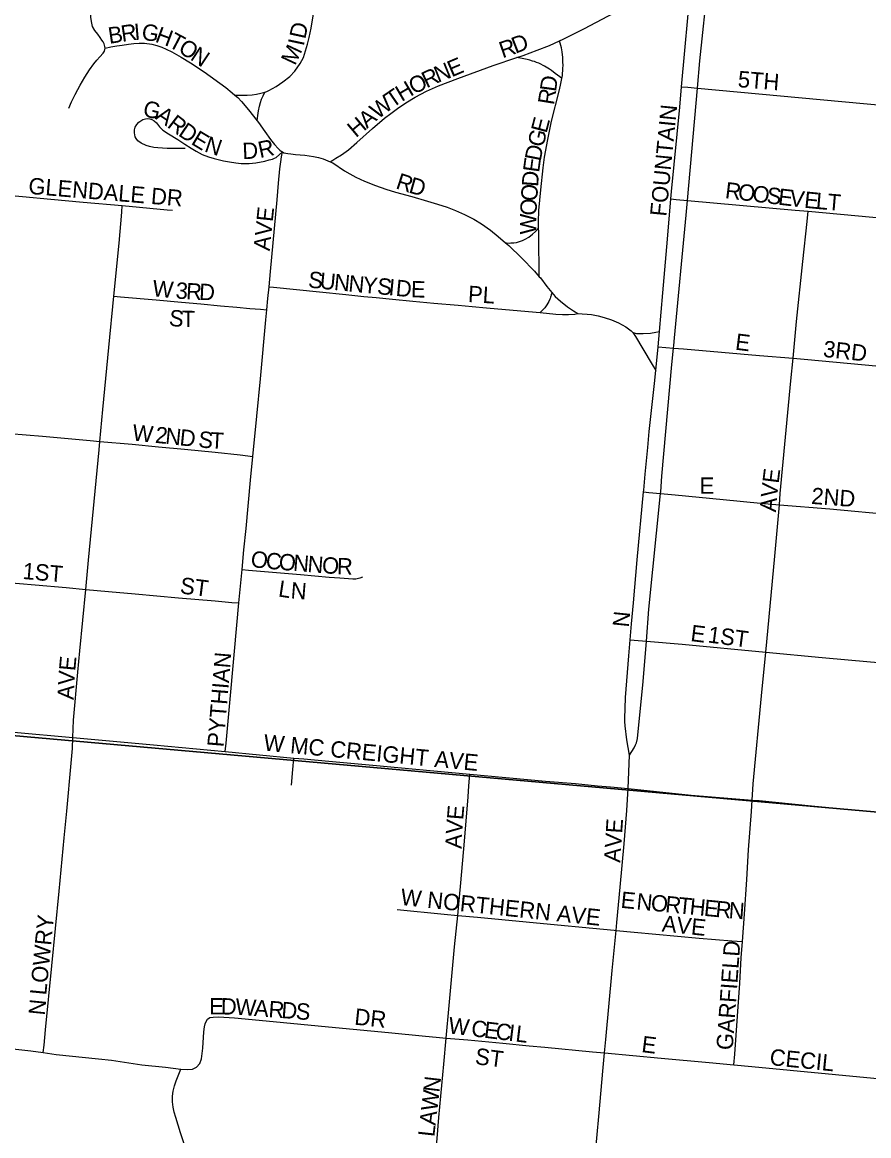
# Model space of a CAD drawing. Extents: x -209 to 4852, y 0 to 905.
# Drawn here: x 111.72 to 121.51, y 290.63 to 303.5 of the extents above; entities that cross this region are included whole.
import ezdxf

# ---------------------------------------------------------------- set-up
doc = ezdxf.new("R2010")
doc.units = 0
for name, color, linetype in [('GM_X_Airport_Location_Class_2', 7, 'Continuous'), ('GM_X_Airport_Location_Class_3', 7, 'Continuous'), ('GM_X_Minor_River', 7, 'Continuous')]:
    doc.layers.add(name, color=color, linetype=linetype)

msp = doc.modelspace()

# ---------------------------------------------------------------- linework, layer by layer
at = {"layer": 'GM_X_Airport_Location_Class_2'}
for points in [[(112.68, 303.197), (112.678, 303.217), (112.67, 303.249), (112.659, 303.27), (112.645, 303.292), (112.624, 303.321), (112.596, 303.36), (112.563, 303.403), (112.537, 303.449), (112.522, 303.506), (112.517, 303.556), (112.517, 303.606), (112.523, 303.652), (112.534, 303.683), (112.554, 303.734), (112.604, 303.849), (112.654, 303.967), (112.714, 304.107), (112.754, 304.205), (112.805, 304.329), (112.845, 304.427), (112.865, 304.477), (112.892, 304.544), (112.913, 304.609)], [(114.528, 302.69), (114.549, 302.698), (114.574, 302.71), (114.659, 302.756), (114.735, 302.809), (114.814, 302.871), (114.873, 302.931), (114.936, 303.019), (114.972, 303.092), (114.998, 303.167), (115.021, 303.246), (115.038, 303.322), (115.061, 303.43), (115.087, 303.572), (115.133, 303.782), (115.181, 304), (115.258, 304.315), (115.274, 304.381)], [(117.931, 303.283), (117.973, 303.302), (118.223, 303.426), (118.491, 303.566), (118.736, 303.686), (118.988, 303.821), (119.004, 303.831), (119.013, 303.838), (119.019, 303.842), (119.025, 303.848), (119.033, 303.854), (119.044, 303.865), (119.054, 303.876), (119.059, 303.884), (119.063, 303.889), (119.066, 303.893), (119.069, 303.897), (119.072, 303.904), (119.081, 303.925), (119.115, 304)], [(119.343, 302.753), (119.453, 303.973)], [(119.526, 302.737), (119.554, 303.051), (119.651, 303.964)], [(117.438, 303.089), (117.511, 303.114), (117.673, 303.173), (117.817, 303.23), (117.931, 303.283)], [(117.96, 302.847), (117.962, 302.861), (117.965, 302.882), (117.972, 302.964), (117.973, 303.002), (117.972, 303.038), (117.97, 303.089), (117.963, 303.154), (117.954, 303.202), (117.939, 303.257), (117.931, 303.283)], [(112.26, 302.506), (112.293, 302.578), (112.333, 302.662), (112.365, 302.719), (112.392, 302.772), (112.445, 302.861), (112.5, 302.946), (112.551, 303.017), (112.585, 303.058), (112.62, 303.098), (112.657, 303.139), (112.672, 303.165), (112.678, 303.182), (112.68, 303.197)], [(112.68, 303.197), (112.749, 303.212), (112.817, 303.225), (112.879, 303.234), (112.951, 303.245), (113.013, 303.253), (113.073, 303.257), (113.138, 303.257), (113.222, 303.245), (113.278, 303.23), (113.335, 303.21), (113.386, 303.188), (113.451, 303.157), (113.56, 303.095), (113.666, 303.03), (113.824, 302.924), (114.075, 302.744), (114.151, 302.681), (114.182, 302.654)], [(115.281, 301.885), (115.314, 301.903), (115.349, 301.926), (115.413, 301.967), (115.493, 302.025), (115.591, 302.108), (115.773, 302.268), (115.911, 302.39), (115.983, 302.444), (116.059, 302.502), (116.156, 302.566), (116.263, 302.631), (116.396, 302.7), (116.534, 302.761), (116.645, 302.804), (116.757, 302.846), (117.165, 302.997), (117.438, 303.089)], [(117.96, 302.847), (117.935, 302.867), (117.884, 302.906), (117.841, 302.938), (117.816, 302.955), (117.796, 302.968), (117.778, 302.98), (117.76, 302.991), (117.743, 302.999), (117.717, 303.013), (117.693, 303.024), (117.668, 303.033), (117.644, 303.043), (117.621, 303.049), (117.588, 303.059), (117.558, 303.068), (117.502, 303.08), (117.438, 303.089)], [(117.689, 301.117), (117.689, 301.191), (117.695, 301.323), (117.715, 301.562), (117.743, 301.817), (117.759, 301.94), (117.796, 302.141), (117.84, 302.353), (117.927, 302.701), (117.944, 302.771), (117.957, 302.828), (117.96, 302.847)], [(114.182, 302.654), (114.275, 302.654), (114.324, 302.654), (114.38, 302.658), (114.429, 302.665), (114.479, 302.676), (114.528, 302.69)], [(114.182, 302.654), (114.213, 302.628), (114.258, 302.582), (114.338, 302.487), (114.438, 302.357)], [(114.438, 302.357), (114.447, 302.421), (114.454, 302.473), (114.465, 302.528), (114.476, 302.569), (114.49, 302.609), (114.507, 302.648), (114.528, 302.69)], [(119.22, 301.456), (119.227, 301.541), (119.321, 302.516), (119.343, 302.753)], [(119.343, 302.753), (119.415, 302.747), (119.526, 302.737)], [(119.411, 301.438), (119.526, 302.737)], [(119.526, 302.737), (121.445, 302.558), (123.103, 302.408), (123.276, 302.392)], [(113.605, 302.04), (113.397, 302.04), (113.292, 302.045), (113.245, 302.05), (113.195, 302.062), (113.155, 302.074), (113.099, 302.101), (113.06, 302.127), (113.039, 302.154), (113.03, 302.173), (113.023, 302.195), (113.019, 302.221), (113.021, 302.256), (113.029, 302.284), (113.047, 302.316), (113.071, 302.342), (113.095, 302.36), (113.118, 302.373), (113.146, 302.383), (113.171, 302.387), (113.196, 302.383), (113.22, 302.375), (113.246, 302.36), (113.275, 302.334), (113.311, 302.288), (113.349, 302.249), (113.415, 302.207), (113.52, 302.141), (113.603, 302.09), (113.677, 302.041), (113.733, 302.006), (113.803, 301.97), (113.875, 301.942), (113.942, 301.922), (114.048, 301.897), (114.12, 301.883), (114.192, 301.871), (114.254, 301.866), (114.3, 301.866), (114.346, 301.867), (114.423, 301.874), (114.527, 301.893), (114.577, 301.906), (114.617, 301.917), (114.637, 301.925), (114.656, 301.936), (114.73, 302)], [(114.438, 302.357), (114.452, 302.339), (114.525, 302.235), (114.593, 302.143), (114.637, 302.083), (114.68, 302.038), (114.699, 302.021), (114.714, 302.009), (114.73, 302)], [(114.575, 300.44), (114.592, 300.616), (114.671, 301.445), (114.686, 301.636), (114.702, 301.805), (114.71, 301.884), (114.718, 301.941), (114.73, 302)], [(114.73, 302), (114.748, 301.99), (114.769, 301.984), (114.793, 301.979), (114.826, 301.975), (114.88, 301.97), (114.99, 301.962), (115.091, 301.946), (115.147, 301.933), (115.201, 301.918), (115.256, 301.897), (115.281, 301.885)], [(115.281, 301.885), (115.311, 301.871), (115.449, 301.78), (115.509, 301.745), (115.579, 301.709), (115.679, 301.662), (115.805, 301.611), (115.925, 301.569), (116.036, 301.534), (116.226, 301.483), (116.406, 301.431), (116.524, 301.396), (116.634, 301.36), (116.731, 301.323), (116.836, 301.275), (116.942, 301.222), (117.03, 301.169), (117.133, 301.094), (117.223, 301.021), (117.308, 300.947)], [(111.409, 301.513), (111.475, 301.507), (111.728, 301.484), (112.053, 301.454), (112.429, 301.419), (112.879, 301.378)], [(112.783, 300.332), (112.844, 300.944), (112.874, 301.304), (112.879, 301.378)], [(112.879, 301.378), (113.397, 301.331), (113.458, 301.325)], [(119.086, 299.922), (119.128, 300.371), (119.181, 300.989), (119.22, 301.456)], [(119.22, 301.456), (119.279, 301.45), (119.411, 301.438)], [(119.25, 299.733), (119.252, 299.761), (119.261, 299.851), (119.396, 301.269), (119.411, 301.438)], [(119.411, 301.438), (120.656, 301.327), (120.805, 301.313)], [(120.631, 299.614), (120.672, 300.038), (120.744, 300.733), (120.793, 301.196), (120.805, 301.313)], [(120.805, 301.313), (122.3, 301.176), (122.981, 301.11), (123.139, 301.095)], [(117.308, 300.947), (117.319, 300.947), (117.35, 300.946), (117.371, 300.947), (117.383, 300.948), (117.39, 300.948), (117.398, 300.949), (117.406, 300.95), (117.435, 300.954), (117.469, 300.962), (117.505, 300.976), (117.536, 300.992), (117.576, 301.014), (117.622, 301.047), (117.655, 301.078), (117.674, 301.099), (117.681, 301.106), (117.689, 301.117)], [(117.699, 300.556), (117.699, 300.581), (117.698, 300.687), (117.694, 300.901), (117.694, 301.016), (117.693, 301.047), (117.692, 301.075), (117.689, 301.117)], [(117.308, 300.947), (117.345, 300.916), (117.493, 300.776), (117.645, 300.621), (117.699, 300.556)], [(117.699, 300.556), (117.712, 300.543), (117.785, 300.444), (117.844, 300.375)], [(112.621, 298.654), (112.653, 299.024), (112.737, 299.858), (112.771, 300.214), (112.783, 300.332)], [(112.783, 300.332), (112.857, 300.325), (113.272, 300.288), (113.562, 300.263), (113.787, 300.243), (114.015, 300.222), (114.205, 300.205), (114.352, 300.191), (114.476, 300.18), (114.55, 300.173)], [(114.55, 300.173), (114.562, 300.305), (114.575, 300.44)], [(114.575, 300.44), (114.627, 300.435), (115.158, 300.382), (115.463, 300.351), (115.672, 300.33), (115.815, 300.316), (116.004, 300.297), (116.239, 300.275), (116.48, 300.253), (116.762, 300.227), (116.923, 300.213), (117.088, 300.198), (117.308, 300.178), (117.71, 300.142)], [(117.844, 300.375), (117.843, 300.37), (117.842, 300.368), (117.84, 300.359), (117.837, 300.348), (117.834, 300.338), (117.833, 300.332), (117.831, 300.328), (117.83, 300.325), (117.828, 300.319), (117.824, 300.307), (117.819, 300.296), (117.808, 300.272), (117.796, 300.25), (117.786, 300.232), (117.779, 300.221), (117.771, 300.209), (117.762, 300.198), (117.747, 300.182), (117.71, 300.142)], [(117.844, 300.375), (117.882, 300.33), (117.943, 300.275), (118.025, 300.208), (118.093, 300.161), (118.145, 300.13)], [(114.389, 298.479), (114.436, 298.945), (114.475, 299.378), (114.54, 300.058), (114.55, 300.173)], [(117.71, 300.142), (117.888, 300.126), (117.967, 300.121), (118.035, 300.121), (118.111, 300.126), (118.145, 300.13)], [(118.145, 300.13), (118.195, 300.129), (118.252, 300.126), (118.303, 300.119), (118.379, 300.105), (118.45, 300.087), (118.535, 300.057), (118.615, 300.024), (118.697, 299.979), (118.731, 299.955), (118.759, 299.931), (118.778, 299.912)], [(118.778, 299.912), (118.822, 299.902), (118.9, 299.899), (118.982, 299.905), (119.044, 299.915), (119.086, 299.922)], [(118.778, 299.912), (118.81, 299.866), (118.894, 299.722), (119.003, 299.544), (119.046, 299.475)], [(119.071, 299.747), (119.086, 299.922)], [(119.046, 299.475), (119.071, 299.747)], [(119.071, 299.747), (119.162, 299.74), (119.25, 299.733)], [(119.101, 298.052), (119.103, 298.072), (119.116, 298.252), (119.229, 299.543), (119.25, 299.733)], [(119.25, 299.733), (119.366, 299.724), (120.244, 299.647), (120.631, 299.614)], [(120.473, 297.922), (120.484, 298.052), (120.605, 299.352), (120.631, 299.614)], [(120.631, 299.614), (120.803, 299.599), (121.919, 299.498), (122.284, 299.46), (122.776, 299.416), (122.969, 299.399)], [(118.904, 298.071), (118.905, 298.089), (118.923, 298.274), (118.952, 298.583), (118.97, 298.769), (119.032, 299.324), (119.046, 299.475)], [(111.149, 298.783), (111.212, 298.777), (111.58, 298.745), (111.957, 298.713), (112.507, 298.664), (112.621, 298.654)], [(112.458, 296.944), (112.49, 297.282), (112.611, 298.557), (112.621, 298.654)], [(112.621, 298.654), (112.995, 298.621), (113.298, 298.592), (113.6, 298.563), (113.951, 298.529), (114.241, 298.497), (114.389, 298.479)], [(114.264, 297.173), (114.286, 297.4), (114.311, 297.649), (114.363, 298.205), (114.389, 298.479)], [(118.749, 296.362), (118.764, 296.544), (118.786, 296.79), (118.829, 297.285), (118.904, 298.071)], [(118.904, 298.071), (118.965, 298.065), (119.101, 298.052)], [(118.936, 296.347), (118.965, 296.714), (119.101, 298.052)], [(119.101, 298.052), (119.268, 298.036), (119.823, 297.981), (120.257, 297.94), (120.473, 297.922)], [(120.318, 296.219), (120.329, 296.336), (120.419, 297.329), (120.473, 297.922)], [(120.473, 297.922), (121.057, 297.873), (121.801, 297.804), (122.795, 297.717)], [(114.226, 296.788), (114.264, 297.173)], [(114.264, 297.173), (114.338, 297.167), (114.661, 297.14), (114.94, 297.116), (115.271, 297.085), (115.393, 297.076), (115.545, 297.066), (115.561, 297.066), (115.577, 297.067), (115.594, 297.07), (115.61, 297.073), (115.629, 297.079), (115.66, 297.089)], [(110.989, 297.08), (111.029, 297.076), (111.142, 297.064), (111.512, 297.029), (111.873, 296.995), (112.229, 296.966), (112.458, 296.944)], [(112.308, 295.231), (112.315, 295.432), (112.365, 295.986), (112.389, 296.233), (112.458, 296.944)], [(112.458, 296.944), (112.721, 296.92), (113.027, 296.892), (113.531, 296.847), (113.953, 296.81), (114.147, 296.794), (114.226, 296.788)], [(114.069, 295.069), (114.079, 295.167), (114.116, 295.548), (114.176, 296.231), (114.226, 296.788)], [(118.741, 295.027), (118.711, 295.207), (118.693, 295.367), (118.688, 295.416), (118.687, 295.454), (118.69, 295.566), (118.695, 295.693), (118.733, 296.175), (118.749, 296.362)], [(118.741, 295.027), (118.794, 295.112), (118.811, 295.148), (118.821, 295.171), (118.833, 295.221), (118.899, 295.881), (118.936, 296.347)], [(118.749, 296.362), (118.796, 296.358), (118.936, 296.347)], [(118.936, 296.347), (119.351, 296.31), (120.318, 296.219)], [(120.159, 294.509), (120.172, 294.696), (120.268, 295.713), (120.318, 296.219)], [(120.318, 296.219), (120.967, 296.157), (121.526, 296.106), (121.837, 296.078), (122.621, 296.021)], [(110.822, 295.363), (111.625, 295.294), (112.308, 295.231)], [(111.966, 291.591), (111.975, 291.675), (111.992, 291.854), (112.067, 292.593), (112.109, 293.024), (112.149, 293.456), (112.209, 294.073), (112.237, 294.382), (112.288, 294.935), (112.303, 295.105), (112.308, 295.231)], [(112.308, 295.231), (113.239, 295.147), (114.069, 295.069)], [(114.069, 295.069), (114.863, 294.995)], [(114.835, 294.682), (114.851, 294.863), (114.863, 294.995)], [(114.863, 294.995), (114.977, 294.984), (115.266, 294.957), (115.816, 294.907), (116.065, 294.884), (116.897, 294.808)], [(118.727, 294.641), (118.741, 295.027)], [(116.757, 293.176), (116.766, 293.265), (116.793, 293.553), (116.835, 294.035), (116.876, 294.546), (116.886, 294.673), (116.897, 294.808)], [(116.897, 294.808), (117.77, 294.729), (118.117, 294.699), (118.373, 294.675), (118.521, 294.662), (118.727, 294.641)], [(118.586, 293.002), (118.595, 293.095), (118.634, 293.504), (118.68, 294.002), (118.71, 294.387), (118.727, 294.641)], [(118.727, 294.641), (119.452, 294.567), (120.159, 294.509)], [(120.047, 292.873), (120.071, 293.19), (120.097, 293.592), (120.118, 293.935), (120.15, 294.377), (120.159, 294.509)], [(120.159, 294.509), (120.239, 294.504), (120.843, 294.443), (121.935, 294.339), (122.283, 294.308), (122.453, 294.293)], [(116.055, 293.243), (116.598, 293.19), (116.757, 293.176)], [(116.623, 291.758), (116.659, 292.136), (116.72, 292.815), (116.757, 293.176)], [(116.757, 293.176), (116.984, 293.156), (117.828, 293.075), (118.319, 293.028), (118.564, 293.004), (118.586, 293.002)], [(118.453, 291.587), (118.467, 291.742), (118.541, 292.541), (118.586, 293.002)], [(118.586, 293.002), (118.795, 292.981), (119.294, 292.936), (119.548, 292.913), (119.925, 292.883), (120.047, 292.873)], [(119.948, 291.449), (119.957, 291.574), (119.988, 292.013), (120.015, 292.394), (120.033, 292.687), (120.047, 292.873)], [(113.555, 291.401), (113.632, 291.394), (113.69, 291.399), (113.738, 291.424), (113.774, 291.466), (113.794, 291.519), (113.811, 291.643), (113.823, 291.832), (113.83, 291.887), (113.836, 291.923), (113.848, 291.951), (113.866, 291.976), (113.89, 291.995)], [(113.89, 291.995), (113.928, 292), (113.991, 292.003), (114.176, 291.992), (114.544, 291.958), (115.342, 291.881), (115.955, 291.822), (116.385, 291.78), (116.508, 291.769), (116.623, 291.758)], [(110.482, 291.757), (110.633, 291.741), (111.436, 291.655), (111.823, 291.61), (111.966, 291.591)], [(116.475, 290.093), (116.519, 290.597), (116.538, 290.842), (116.594, 291.457), (116.623, 291.758)], [(116.623, 291.758), (116.871, 291.738), (117.278, 291.7), (117.581, 291.671), (117.763, 291.654), (118.315, 291.6), (118.453, 291.587)], [(111.966, 291.591), (112.116, 291.57), (112.603, 291.52), (112.753, 291.505), (113.107, 291.449), (113.378, 291.424), (113.555, 291.401)], [(118.303, 289.934), (118.311, 290.043), (118.336, 290.308), (118.391, 290.894), (118.434, 291.377), (118.453, 291.587)], [(118.453, 291.587), (119.108, 291.528), (119.663, 291.477), (119.948, 291.449)], [(119.948, 291.449), (120.154, 291.43), (121.566, 291.294), (121.996, 291.253), (122.145, 291.24), (122.235, 291.231)], [(113.908, 289.721), (113.862, 289.837), (113.829, 289.921), (113.792, 290.03), (113.724, 290.198), (113.635, 290.426), (113.554, 290.662), (113.497, 290.841), (113.479, 290.901), (113.466, 290.961), (113.459, 291.023), (113.461, 291.086), (113.469, 291.147), (113.483, 291.207), (113.503, 291.265), (113.555, 291.401)]]:
    msp.add_lwpolyline(points, dxfattribs=at)
at = {"layer": 'GM_X_Minor_River'}
for points in [[(112.672, 315.623), (132.725, 313.81), (130.833, 293.553), (110.863, 295.32)], [(110.863, 295.32), (130.833, 293.553), (129.104, 273.545), (108.909, 275.428)]]:
    msp.add_lwpolyline(points, close=True, dxfattribs=at)

# ---------------------------------------------------------------- texts
at = {"layer": 'GM_X_Airport_Location_Class_3'}
for s, height, rotation, p in [('B', 0.189, 8.3602, (112.73, 303.248)), ('R', 0.189, 8.3362, (112.878, 303.27)), ('I', 0.189, 5.0757, (113.024, 303.291)), ('G', 0.189, 350.9365, (113.094, 303.299)), ('H', 0.189, 339.6845, (113.249, 303.275)), ('D', 0.189, 77.6229, (114.993, 303.296)), ('T', 0.189, 332.1397, (113.4, 303.22)), ('O', 0.189, 327.4132, (113.514, 303.16)), ('I', 0.189, 78.0535, (114.976, 303.215)), ('R', 0.189, 19.0264, (117.274, 303.08)), ('D', 0.189, 21.2096, (117.423, 303.132)), ('N', 0.189, 326.4373, (113.654, 303.071)), ('M', 0.189, 64.8687, (114.876, 302.989)), ('N', 0.189, 22.0734, (116.529, 302.796)), ('E', 0.189, 22.9431, (116.686, 302.86)), ('O', 0.189, 26.9462, (116.249, 302.658)), ('R', 0.189, 25.4247, (116.396, 302.733)), ('5TH', 0.1894, 355.4282, (119.988, 302.748)), ('H', 0.189, 30.4578, (116.108, 302.575)), ('D', 0.189, 82.1107, (117.891, 302.688)), ('W', 0.189, 38.0033, (115.833, 302.37)), ('T', 0.189, 34.607, (116.001, 302.501)), ('R', 0.189, 80.7812, (117.867, 302.535)), ('G', 0.189, 346.7219, (113.107, 302.416)), ('A', 0.189, 325.6491, (113.252, 302.386)), ('FOUNTAIN', 0.1894, 84.3612, (119.166, 301.248)), ('R', 0.189, 322.5425, (113.388, 302.293)), ('H', 0.189, 39.9707, (115.579, 302.157)), ('A', 0.189, 39.9707, (115.707, 302.264)), ('E', 0.189, 75.3009, (117.782, 302.207)), ('D', 0.189, 325.7315, (113.516, 302.195)), ('E', 0.189, 328.9183, (113.664, 302.095)), ('G', 0.189, 77.3527, (117.746, 302.046)), ('N', 0.189, 341.4934, (113.819, 302.007)), ('R', 0.189, 12.1769, (114.471, 301.927)), ('D', 0.189, 2.6671, (114.271, 301.915)), ('D', 0.189, 78.8272, (117.714, 301.884)), ('E', 0.189, 82.2447, (117.696, 301.755)), ('R', 0.189, 342.0259, (116.03, 301.58)), ('D', 0.189, 85.8443, (117.684, 301.592)), ('GLENDALE DR', 0.18939, 355.2836, (111.789, 301.515)), ('D', 0.189, 344.2388, (116.18, 301.531)), ('O', 0.189, 86.0405, (117.673, 301.426)), ('R', 0.189, 353.1341, (119.839, 301.465)), ('O', 0.189, 353.1408, (119.988, 301.447)), ('O', 0.189, 353.1216, (120.154, 301.427)), ('S', 0.189, 353.1421, (120.319, 301.407)), ('E', 0.189, 353.1519, (120.452, 301.391)), ('V', 0.189, 353.1755, (120.584, 301.375)), ('E', 0.189, 354.3007, (120.754, 301.355)), ('L', 0.189, 355.1896, (120.89, 301.341)), ('T', 0.189, 355.2142, (121.023, 301.33)), ('AVE', 0.1894, 84.0895, (114.583, 300.85)), ('O', 0.189, 87.7478, (117.666, 301.261)), ('W', 0.189, 89.9159, (117.666, 301.046)), ('S', 0.189, 354.6102, (115.022, 300.432)), ('U', 0.189, 354.6207, (115.155, 300.419)), ('N', 0.189, 354.6312, (115.321, 300.404)), ('N', 0.189, 354.6156, (115.487, 300.388)), ('W', 0.189, 354.6123, (113.222, 300.332)), ('3', 0.189, 355.7113, (113.491, 300.306)), ('R', 0.189, 357.1338, (113.613, 300.297)), ('D', 0.189, 357.3969, (113.764, 300.29)), ('Y', 0.189, 354.6088, (115.653, 300.372)), ('S', 0.189, 354.6197, (115.819, 300.357)), ('I', 0.189, 354.6234, (115.951, 300.344)), ('D', 0.189, 354.6312, (116.034, 300.336)), ('E', 0.189, 358.1461, (116.213, 300.32)), ('PL', 0.1894, 356.4254, (116.871, 300.265)), ('S', 0.189, 353.4849, (113.412, 299.992)), ('T', 0.189, 358.8897, (113.564, 299.976)), ('E', 0.189, 352.8817, (119.956, 299.715)), ('3RD', 0.1894, 353.6571, (120.972, 299.632)), ('W', 0.189, 354.1723, (112.989, 298.665)), ('2', 0.189, 354.1894, (113.254, 298.638)), ('N', 0.189, 354.1763, (113.37, 298.626)), ('D', 0.189, 354.1684, (113.536, 298.609)), ('S', 0.189, 354.1731, (113.752, 298.587)), ('T', 0.189, 356.7969, (113.894, 298.573)), ('E', 0.189, 82.9326, (120.464, 298.162)), ('E', 0.189, 0, (119.552, 298.048)), ('V', 0.189, 83.8674, (120.446, 297.997)), ('A', 0.189, 85.4487, (120.433, 297.832)), ('2ND', 0.1894, 355.766, (120.838, 297.932)), ('O', 0.189, 352.0183, (114.355, 297.207)), ('C', 0.189, 355.6165, (114.533, 297.183)), ('O', 0.189, 355.5812, (114.683, 297.171)), ('1ST', 0.1894, 355.0241, (111.722, 297.065)), ('N', 0.189, 355.5812, (114.849, 297.158)), ('N', 0.189, 355.5812, (115.015, 297.145)), ('O', 0.189, 355.5812, (115.182, 297.133)), ('R', 0.189, 358.4975, (115.358, 297.119)), ('ST', 0.1894, 352.8783, (113.54, 296.898)), ('L', 0.189, 351.4179, (114.675, 296.863)), ('N', 0.189, 355.4967, (114.821, 296.841)), ('N', 0.189, 84.2937, (118.733, 296.5)), ('E', 0.189, 352.8514, (119.44, 296.348)), ('1ST', 0.1894, 352.5722, (119.64, 296.331)), ('PYTHIAN', 0.1894, 85.3167, (114.05, 295.116)), ('E', 0.189, 84.7462, (112.335, 295.996)), ('V', 0.189, 86.4346, (112.325, 295.831)), ('A', 0.189, 86.939, (112.316, 295.665)), ('W MC CREIGHT AVE', 0.18939, 354.54, (114.506, 295.082)), ('E', 0.189, 85.4315, (116.819, 294.275)), ('V', 0.189, 85.6683, (116.806, 294.109)), ('AVE', 0.1894, 86.183, (118.633, 293.783)), ('A', 0.189, 87.5731, (116.8, 293.944)), ('W NORTHERN AVE', 0.18939, 354.0139, (116.089, 293.298)), ('E', 0.189, 354.4444, (118.634, 293.265)), ('N', 0.189, 354.4395, (118.816, 293.247)), ('O', 0.189, 354.462, (118.982, 293.231)), ('R', 0.189, 354.4296, (119.148, 293.215)), ('T', 0.189, 354.4529, (119.298, 293.201)), ('H', 0.189, 354.462, (119.43, 293.188)), ('E', 0.189, 354.4444, (119.596, 293.172)), ('R', 0.189, 354.4575, (119.729, 293.159)), ('N', 0.189, 355.9165, (119.883, 293.144)), ('LOWRY', 0.1894, 84.398, (112, 292.249)), ('AVE', 0.1894, 354.0977, (119.11, 292.991)), ('GARFIELD', 0.1894, 85.9173, (119.933, 291.615)), ('E', 0.189, 359.918, (113.885, 292.032)), ('D', 0.189, 359.1038, (114.018, 292.032)), ('W', 0.189, 356.1636, (114.182, 292.029)), ('N', 0.189, 84.2937, (111.983, 292.016)), ('A', 0.189, 355.6901, (114.398, 292.015)), ('R', 0.189, 355.6739, (114.564, 292.002)), ('D', 0.189, 355.6798, (114.713, 291.991)), ('S', 0.189, 355.6788, (114.879, 291.978)), ('DR', 0.1894, 353.9946, (115.556, 291.915)), ('W', 0.189, 353.0397, (116.64, 291.815)), ('C', 0.189, 353.0571, (116.904, 291.782)), ('E', 0.189, 353.0173, (117.053, 291.764)), ('C', 0.189, 353.0336, (117.186, 291.748)), ('I', 0.189, 353.0309, (117.335, 291.73)), ('L', 0.189, 353.0243, (117.417, 291.72)), ('E', 0.189, 352.8514, (118.873, 291.598)), ('ST', 0.1894, 352.8783, (116.949, 291.458)), ('CECIL', 0.1894, 354.2927, (120.355, 291.448)), ('N', 0.189, 83.3671, (116.544, 291.125)), ('W', 0.189, 83.3609, (116.519, 290.909)), ('A', 0.189, 83.3846, (116.5, 290.744)), ('L', 0.189, 83.8137, (116.485, 290.612))]:
    msp.add_text(s, height=height, rotation=rotation, dxfattribs=at).set_placement(p)

doc.saveas('drawing.dxf')
